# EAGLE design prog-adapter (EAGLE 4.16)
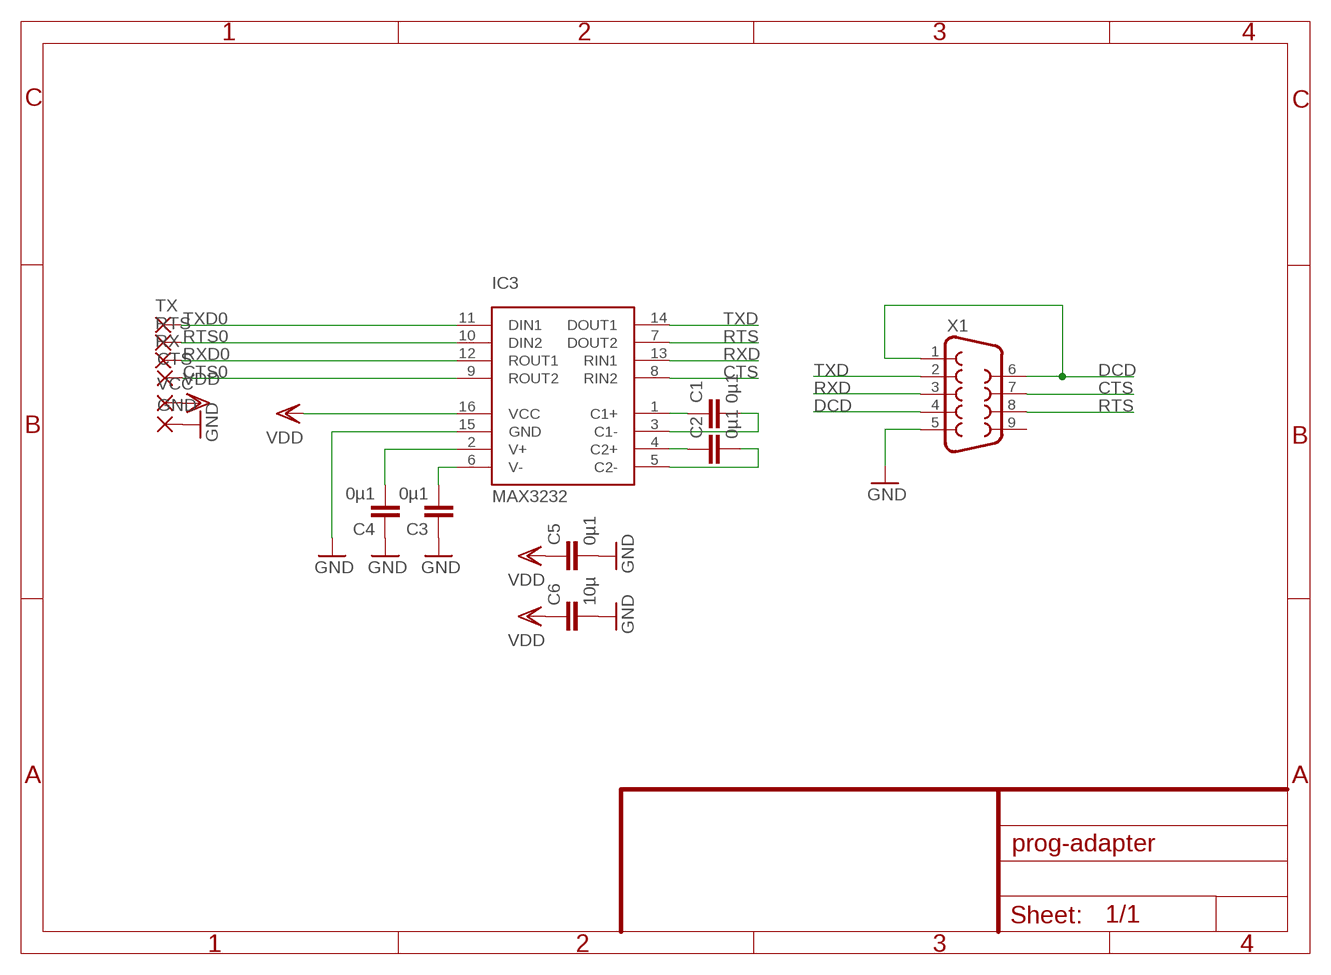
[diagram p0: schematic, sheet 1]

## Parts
C1  0µ1  C-EUC0805K  [C0805K]
C2  0µ1  C-EUC0805K  [C0805K]
C3  0µ1  C-EUC0805K  [C0805K]
C4  0µ1  C-EUC0805K  [C0805K]
C5  0µ1  C-EUC0805K  [C0805K]
C6  10µ  C-EUC1206K  [C1206K]
CTS  SMD5  [SMD5]
GND  SMD5  [SMD5]
IC3  MAX3232  SN65C3232SO16  [SO16]
RTS  SMD5  [SMD5]
RX  SMD5  [SMD5]
TX  SMD5  [SMD5]
VCC  SMD5  [SMD5]
X1  F09D  [F09D]

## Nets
CTS: IC3.8(RIN2) X1.7
CTS0: CTS.1(P) IC3.9(ROUT2)
DCD: X1.1 X1.4 X1.6
GND: C3.1 C4.1 C5.2 C6.2 GND.1(P) IC3.15(GND) X1.5
N$1: C1.1 IC3.1(C1+)
N$2: C2.1 IC3.4(C2+)
N$3: C3.2 IC3.6(V-)
N$4: C4.2 IC3.2(V+)
N$5: C1.2 IC3.3(C1-)
N$6: C2.2 IC3.5(C2-)
RTS: IC3.7(DOUT2) X1.8
RTS0: IC3.10(DIN2) RTS.1(P)
RXD: IC3.13(RIN1) X1.3
RXD0: IC3.12(ROUT1) RX.1(P)
TXD: IC3.14(DOUT1) X1.2
TXD0: IC3.11(DIN1) TX.1(P)
VDD: C5.1 C6.1 IC3.16(VCC) VCC.1(P)
Unconnected: X1.9

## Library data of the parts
C1-C6 = rcl:C-EU: CAPACITOR, European symbol
CTS GND RTS RX TX VCC = wirepad:SMD5: SMD PAD
IC3 = bauteile:SN65C3232
X1 = con-subd:F09: SUB-D

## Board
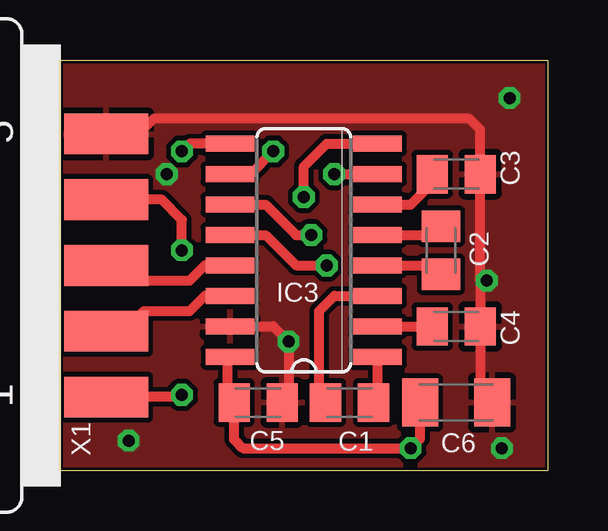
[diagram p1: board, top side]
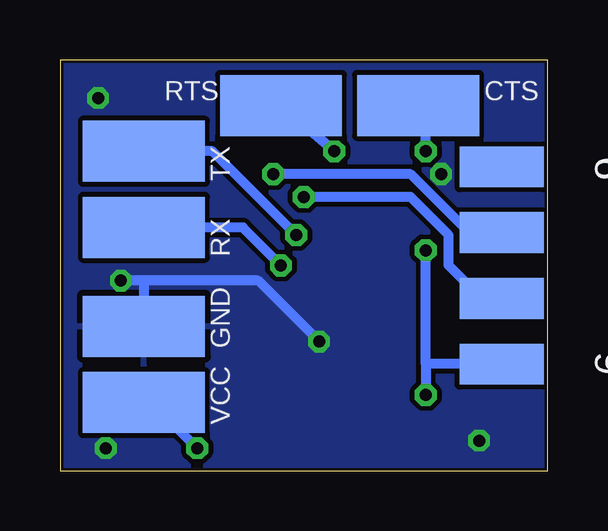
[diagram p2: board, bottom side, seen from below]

Size 20.32 x 17.14 mm. Coordinates in mm from the lower left corner, seen from the top.
Outline: 0,0 0,17.14 20.32,17.14 20.32,0 0,0
Copper layers (1*16): Top 0.035mm / dielectric 1.5mm / Bottom 0.035mm
Design rules "default": minimum track width 10mil, minimum drill 12mil, track to track 8mil, track to pad 8mil, pad to pad 8mil, via to via 8mil, smd to smd 4mil, copper to edge 5mil, drill to drill 8mil, minimum pad ring 10mil, minimum via ring 8mil, stop-mask expansion 4mil, vias tented up to drill 0mil, thermal gap 10mil

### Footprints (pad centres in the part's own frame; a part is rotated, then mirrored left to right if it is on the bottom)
C0805K = smd 1.3 x 1.6: 1 -1,0; 2 1,0
C1206K = smd 1.5 x 2: 1 -1.5,0; 2 1.5,0
SMD5 = smd 2.54 x 5.08: 1 0,0
SO16 = smd 0.66 x 2.032: 1 -4.445,-3.073; 2 -3.175,-3.073; 3 -1.905,-3.073; 4 -0.635,-3.073; 5 0.635,-3.073; 6 1.905,-3.073; 7 3.175,-3.073; 8 4.445,-3.073; 9 4.445,3.073; 10 3.175,3.073; 11 1.905,3.073; 12 0.635,3.073; 13 -0.635,3.073; 14 -1.905,3.073; 15 -3.175,3.073; 16 -4.445,3.073
F09D = smd 1.7 x 3.5: 1 -5.486,-6.045; 2 -2.743,-6.045; 3 0,-6.045; 4 2.743,-6.045; 5 5.486,-6.045 | smd 1.7 x 3.5 bottom: 6 -4.115,-6.045; 7 -1.372,-6.045; 8 1.372,-6.045; 9 4.115,-6.045

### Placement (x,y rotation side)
C1  12.06,2.86 180 top
C2  15.88,9.21 90 top
C3  16.51,12.38 180 top
C4  16.51,6.03 180 top
C5  8.26,2.86 0 top
C6  16.51,2.86 0 top
CTS  5.4,15.24 270 bottom
GND  16.83,6.03 90 bottom
IC3  10.16,9.21 90 top
RTS  11.11,15.24 270 bottom
RX  16.83,10.16 270 bottom
TX  16.83,13.34 270 bottom
VCC  16.83,2.86 270 bottom
X1  -4.13,8.57 90 top

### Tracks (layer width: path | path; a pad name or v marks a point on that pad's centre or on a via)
CTS  (via drill 0.5)
  Top 0.406: IC3.8 11.11,13.65 10.16,12.7 v10.16,11.43
  Bottom 0.406: X1.7 2.76,7.2 4.13,8.57 4.13,9.84 5.71,11.43 v10.16,11.43
CTS0  (via drill 0.5)
  Top 0.406: v5.08,13.34 5.4,13.65 IC3.9
  Bottom 0.406: v5.08,13.34 5.08,15.56 CTS.1
DCD  (via drill 0.5)
  Top 0.406: X1.1 4.99,3.09 v5.08,3.17 | X1.4 4.24,11.32 5.08,10.48 v5.08,9.21
  Bottom 0.406: 5.08,4.45 v5.08,3.17 | 5.08,4.45 v5.08,9.21 | X1.6 5.08,4.46 5.08,4.45
GND  (via drill 0.5)
  Top 0.406: IC3.15 8.89,6.03 v9.53,5.4 9.53,2.86 C5.2 | C6.2 17.78,2.86 17.51,3.13 C4.1 17.78,6.03 17.51,6.3 17.51,7.94 | 17.51,7.94 C3.1 17.51,14.24 17.06,14.69 3.9,14.69 3.26,14.06 X1.5 | v17.78,7.94 17.51,7.94
  Bottom 0.406: v9.53,5.4 12.06,7.94 16.83,7.94 | 16.83,7.94 v17.78,7.94 | 16.83,7.94 GND.1
  other vias: 18.73,15.56 2.86,1.27 18.41,0.95 4.45,12.38
  pour Bottom: 0,17.14 0,0 20.32,0 20.32,17.14
  pour Top: 0,17.14 0,0 20.32,0 20.32,17.14
N$1
  Top 0.406: C1.1 13.34,2.86 13.23,2.96 IC3.1
N$2
  Top 0.406: C2.1 15.88,8.57 IC3.4
N$3
  Top 0.406: C3.2 15.88,12.38 14.61,11.11 IC3.6
N$4
  Top 0.406: 15.88,6.03 C4.2 IC3.2
N$5
  Top 0.406: IC3.3 11.43,7.3 10.79,6.67 10.79,2.86 C1.2
N$6
  Top 0.406: C2.2 15.88,9.84 IC3.5
RTS  (via drill 0.5)
  Top 0.406: 12.7,12.38 IC3.7 v11.43,12.38
  Bottom 0.406: X1.8 3.28,9.94 5.71,12.38 v11.43,12.38
RTS0  (via drill 0.5)
  Top 0.406: IC3.10 7.94,12.38 v8.89,13.34
  Bottom 0.406: v8.89,13.34 RTS.1
RXD
  Top 0.406: X1.3 2.86,8.57 3.49,7.94 5.4,7.94 6.03,8.57 IC3.13
RXD0  (via drill 0.5)
  Top 0.406: v11.11,8.57 9.84,8.57 8.57,9.84 IC3.12 6.99,9.84
  Bottom 0.406: RX.1 12.7,10.16 v11.11,8.57
TXD
  Top 0.406: X1.2 2.65,5.83 3.49,6.67 5.4,6.67 6.03,7.3 IC3.14
TXD0  (via drill 0.5)
  Top 0.406: v10.48,9.84 9.84,9.84 8.57,11.11 IC3.11
  Bottom 0.406: TX.1 13.97,13.34 v10.48,9.84
VDD  (via drill 0.5)
  Top 0.406: IC3.16 6.99,4.76 6.99,2.86 C5.1 7.25,1.32 7.62,0.95 v14.61,0.95 15.01,1.36 C6.1
  Bottom 0.406: VCC.1 16.51,2.86 v14.61,0.95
